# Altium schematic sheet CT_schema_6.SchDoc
size 263 x 177 mm
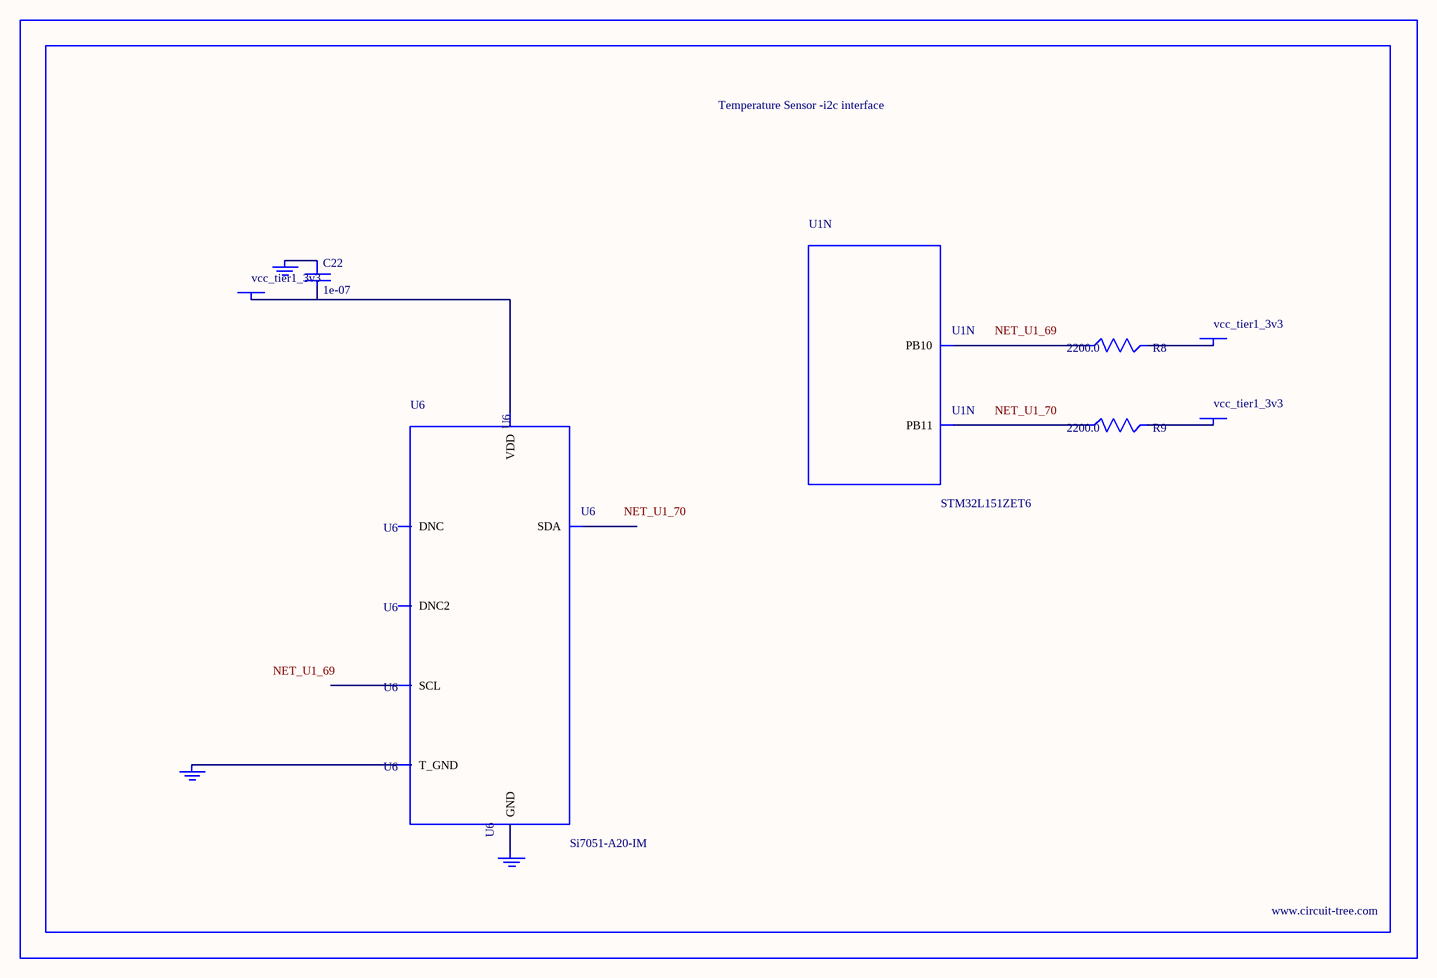
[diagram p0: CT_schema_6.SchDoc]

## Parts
BORDER5  (no value)
C22  1e-07  [C0402]
GND_INSTANCE_5_0  (no value)
GND_INSTANCE_5_1  (no value)
GND_INSTANCE_5_2  (no value)
POWER_INSTANCE_5_0  vcc_tier1_3v3
POWER_INSTANCE_5_1  vcc_tier1_3v3
POWER_INSTANCE_5_2  vcc_tier1_3v3
R8  2200.0  [R0603]
R9  2200.0  [R0603]
U1  STM32L151ZET6  [LQFP144]  (part N of 14)
U6  Si7051-A20-IM  [DFN-6]

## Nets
NetC22_1: C22.1 GND_INSTANCE_5_0.0(GND)
NetC22_2: C22.2 POWER_INSTANCE_5_0.0(PWR) U6.5(VDD)
NetGND_INSTANCE_5_1_0: GND_INSTANCE_5_1.0(GND) U6.7(T_GND)
NetGND_INSTANCE_5_2_0: GND_INSTANCE_5_2.0(GND) U6.2(GND)
NetPOWER_INSTANCE_5_1_0: POWER_INSTANCE_5_1.0(PWR) R8.2
NetPOWER_INSTANCE_5_2_0: POWER_INSTANCE_5_2.0(PWR) R9.2
NetR8_1: R8.1 U1.69(PB10)
NetR9_1: R9.1 U1.70(PB11)

Not connected (* = marked no-connect by the designer): U6 1(SDA) 3(DNC) 4(DNC2) 6(SCL)

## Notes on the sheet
- Labels drawn without touching a wire or pin: NET_U1_69, NET_U1_70

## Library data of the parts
BORDER5 = BORDER_PAGE5
C22 = C0402C104K3RACTU
GND_INSTANCE_5_0-GND_INSTANCE_5_2 = GND
POWER_INSTANCE_5_0-POWER_INSTANCE_5_2 = PWR
R8 R9 = RC0603JR-072K2L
